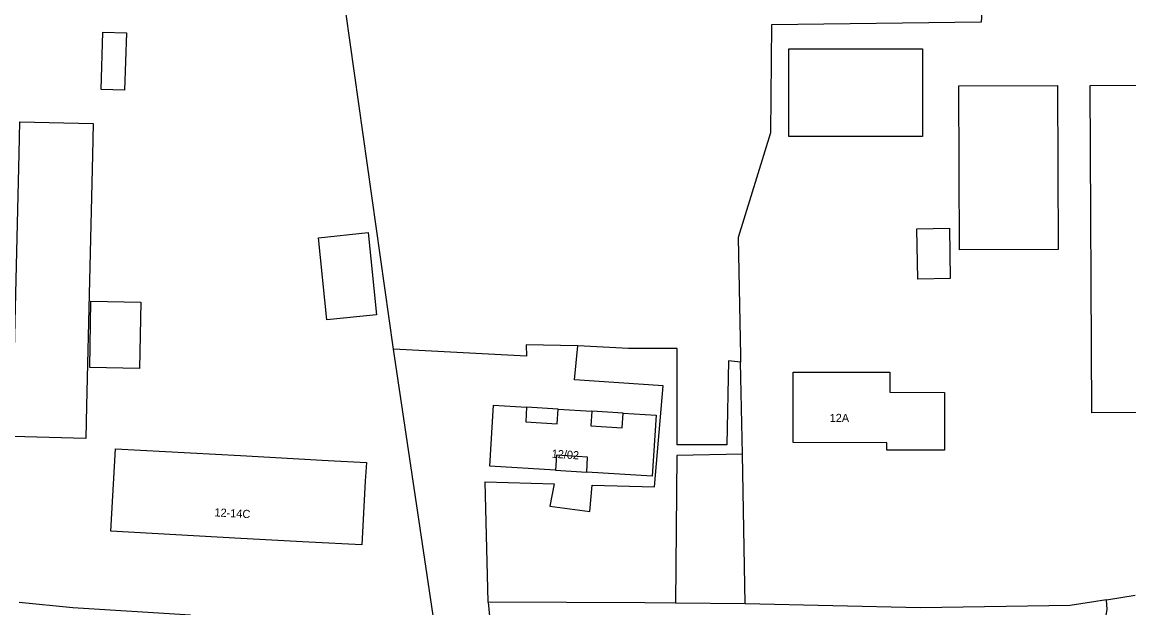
# Model space of a CAD drawing. Extents: x 162515 to 163909, y 388494 to 389773.
# Drawn here: x 162964.9 to 163100.4, y 388975.3 to 389047 of the extents above; entities that cross this region are included whole.
import ezdxf

# ---------------------------------------------------------------- set-up
doc = ezdxf.new("R2010")
doc.units = 0
for name, color, linetype in [('IMGEO_Erf', 7, 'Continuous'), ('IMGEO_Grasland_agrarisch', 7, 'Continuous'), ('IMGEO_Grasland_overig', 7, 'Continuous'), ('IMGEO_Groenvoorziening', 7, 'Continuous'), ('IMGEO_Pand', 7, 'Continuous'), ('IMGEO_Pand_nummerreeks', 7, 'Continuous'), ('IMGEO_Pand_overbouw', 7, 'Continuous'), ('IMGEO_Rijbaan_lokaal_open', 7, 'Continuous')]:
    doc.layers.add(name, color=color, linetype=linetype)

msp = doc.modelspace()

# ---------------------------------------------------------------- linework, layer by layer
at = {"layer": 'IMGEO_Erf'}
for points in [[(163015.35, 388973.53), (163010.38, 389006.95)], [(163021.97, 388975.96), (163021.58, 388990.68), (163030.06, 388990.43), (163029.52, 388987.73), (163034.42, 388987.07), (163034.69, 388990.29), (163042.33, 388990.07), (163043.41, 389002.45), (163032.54, 389003.17), (163032.96, 389007.33)], [(163053.09, 388994.09), (163052.87, 389005.35)]]:
    msp.add_lwpolyline(points, dxfattribs=at)
at = {"layer": 'IMGEO_Grasland_agrarisch'}
for points in [[(163010.38, 389006.95), (163001.87, 389067.02), (163025.18, 389071.12), (163045.89, 389088.41), (163039.38, 389131.14), (163061.71, 389139.9), (163071.79, 389142.1), (163088.75, 389144.55), (163090.38, 389144.83)], [(163104.15, 389082.62), (163099.92, 389084.74), (163090.59, 389084.81), (163090.49, 389081), (163090.49, 389080.12), (163086.78, 389080.16), (163087.31, 389068.38), (163087.29, 389060.46), (163086.5, 389057.2), (163085.39, 389054.65), (163082.52, 389050.13), (163082.33, 389046.97), (163056.67, 389046.65), (163056.53, 389033.42), (163052.56, 389020.59), (163052.85, 389006.12), (163052.87, 389005.35)], [(163032.96, 389007.33), (163026.62, 389007.47), (163026.66, 389006.08), (163010.38, 389006.95)], [(163052.87, 389005.35), (163051.39, 389005.51), (163051.19, 388995.21), (163045.1, 388995.21), (163045.1, 389007), (163039.14, 389007.01), (163032.96, 389007.33)]]:
    msp.add_lwpolyline(points, dxfattribs=at)
at = {"layer": 'IMGEO_Grasland_overig'}
for points in [[(163021.97, 388975.96), (163022.23, 388972.97)], [(163044.9, 388975.85), (163041.16, 388975.89), (163021.97, 388975.96)], [(163053.45, 388975.77), (163044.9, 388975.85)], [(163097.67, 388976.26), (163093.21, 388975.56), (163074.89, 388975.27), (163053.45, 388975.77)]]:
    msp.add_lwpolyline(points, dxfattribs=at)
at = {"layer": 'IMGEO_Groenvoorziening'}
for points in [[(163053.09, 388994.09), (163045.08, 388993.93), (163044.9, 388975.85)], [(163053.45, 388975.77), (163053.09, 388994.09)]]:
    msp.add_lwpolyline(points, dxfattribs=at)
at = {"layer": 'IMGEO_Pand'}
for points in [[(162974.56, 389038.72), (162974.79, 389045.74), (162977.68, 389045.65), (162977.45, 389038.62), (162974.56, 389038.72)], [(163075.16, 389040.94), (163075.16, 389032.96), (163059.53, 389032.96), (163058.79, 389032.96), (163058.79, 389043.7), (163075.16, 389043.7), (163075.16, 389040.94)], [(163079.67, 389019.09), (163079.61, 389039.16), (163091.68, 389039.19), (163091.74, 389019.13), (163079.67, 389019.09)], [(163095.88, 388999.14), (163095.69, 389039.22), (163107.73, 389039.28), (163107.92, 388999.2), (163095.88, 388999.14)], [(162964.61, 389034.78), (162973.6, 389034.57), (162973.51, 389030.67), (162972.8, 389000), (162972.71, 388996.01), (162963.71, 388996.22), (162963.8, 389000), (162964.52, 389030.88), (162964.61, 389034.78)], [(163001.17, 389020.57), (163007.25, 389021.2), (163008.3, 389011.15), (163002.22, 389010.52), (163001.17, 389020.57)], [(163074.47, 389021.67), (163078.45, 389021.73), (163078.55, 389015.58), (163074.57, 389015.52), (163074.47, 389021.67)], [(162979.45, 389012.69), (162979.28, 389004.56), (162973.2, 389004.68), (162973.3, 389012.82), (162979.45, 389012.69)], [(163077.85, 388994.57), (163070.76, 388994.58), (163070.76, 388995.48), (163059.32, 388995.5), (163059.33, 389000), (163059.33, 389004.11), (163071.15, 389004.1), (163071.15, 389001.65), (163077.86, 389001.64), (163077.86, 389000), (163077.85, 388994.57)], [(163022.63, 389000.07), (163026.67, 388999.82), (163026.56, 388998.02), (163030.4, 388997.79), (163030.52, 388999.58), (163034.64, 388999.33), (163034.53, 388997.53), (163038.37, 388997.29), (163038.48, 388999.09), (163042.52, 388998.84), (163042.06, 388991.37), (163034.03, 388991.87), (163034.14, 388993.72), (163030.32, 388993.95), (163030.2, 388992.11), (163022.17, 388992.6), (163022.63, 389000.07)], [(163007.05, 388993.06), (163006.92, 388990.76), (163006.5, 388982.97), (163000, 388983.32), (162991.67, 388983.77), (162975.77, 388984.64), (162976.32, 388994.73), (162991.62, 388993.9), (163002.37, 388993.32), (163007.05, 388993.06)]]:
    msp.add_lwpolyline(points, dxfattribs=at)
at = {"layer": 'IMGEO_Pand_overbouw'}
for points in [[(163030.52, 388999.58), (163026.67, 388999.82), (163026.56, 388998.02), (163030.4, 388997.79)], [(163038.48, 388999.09), (163034.64, 388999.33), (163034.53, 388997.53), (163038.37, 388997.29)], [(163034.03, 388991.87), (163034.14, 388993.72), (163030.32, 388993.95), (163030.2, 388992.11)]]:
    msp.add_lwpolyline(points, close=True, dxfattribs=at)
at = {"layer": 'IMGEO_Rijbaan_lokaal_open'}
for points in [[(162985.53, 388974.35), (162971.11, 388975.28), (162964.53, 388975.92)], [(163095.61, 388970.6), (163095.68, 388970.69), (163097.05, 388972.5), (163097.51, 388973.74), (163097.56, 388973.87), (163097.76, 388975.07), (163097.67, 388976.26)], [(163097.67, 388976.26), (163101.17, 388976.81)]]:
    msp.add_lwpolyline(points, dxfattribs=at)

# ---------------------------------------------------------------- texts
at = {"layer": 'IMGEO_Pand_nummerreeks'}
for s, rotation, p in [('12A', 359.9349, (163063.78, 388998.01)), ('12/02', 356.2586, (163029.72, 388993.65)), ('12-14C', 356.8946, (162988.43, 388986.47))]:
    msp.add_text(s, height=1, rotation=rotation, dxfattribs=at).set_placement(p)

doc.saveas('drawing.dxf')
